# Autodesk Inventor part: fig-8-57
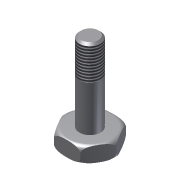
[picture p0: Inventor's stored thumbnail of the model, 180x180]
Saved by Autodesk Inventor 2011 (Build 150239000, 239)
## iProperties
Shininess: 77.0
Length Units: 11269
Angle Units: 11279
Time Units: 11290
Mass Units: 11283
Length Display Precision: 3
Angle Display Precision: 2
Created: 2002-01
Part Number: fig-8-57
Document SubType Name: Modeling
Designer: ***
Density: 1 g/cm^3
Density: 0.0
Volumn: 0.0
Area: 0.0
PropertySet Name: Model Information
Control State: 0
Master: False
Checked Out: False
Author: ***
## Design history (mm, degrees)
sketch "Sketch1"
  geometry: C1 r 25 at (0, 0)
  constraints: 1 centre point
  dimensions: "d0" = 50 diameter of C1
extrude "Extrusion1" new body sketch "Sketch1" distance "d1" = 15; taper "d2" = 0 deg
fillet "Fillet1" dims "d3" = 5
sketch "Sketch2"
  geometry: L1 (25.058, 0)-(12.529, -21.701); L2 (12.529, -21.701)-(-12.529, -21.701); L3 (-12.529, -21.701)-(-25.058, 0); L4 (-25.058, 0)-(-12.529, 21.701); L5 (-12.529, 21.701)-(12.529, 21.701); L6 (12.529, 21.701)-(25.058, 0); 1 further point
  constraints: 12 end point, 11 other
extrude "Extrusion2" sketch "Sketch2" stored distance "d4" = 15; taper "d5" = 0 deg
sketch "Sketch3"
  geometry: C1 r 10.044 at (0, 0); 1 further point
  constraints: 1 centre point, 1 coincident
extrude "Extrusion3" join sketch "Sketch3" distance "d6" = 75; taper "d7" = 0 deg
chamfer "Chamfer1" distance "d8" = 2; stored, may be unused: second distance "d9" = 2, angle "d16" = 45 deg
thread "Thread3" dims "d14" = 30, "d15" = 0
body "Solid1"
